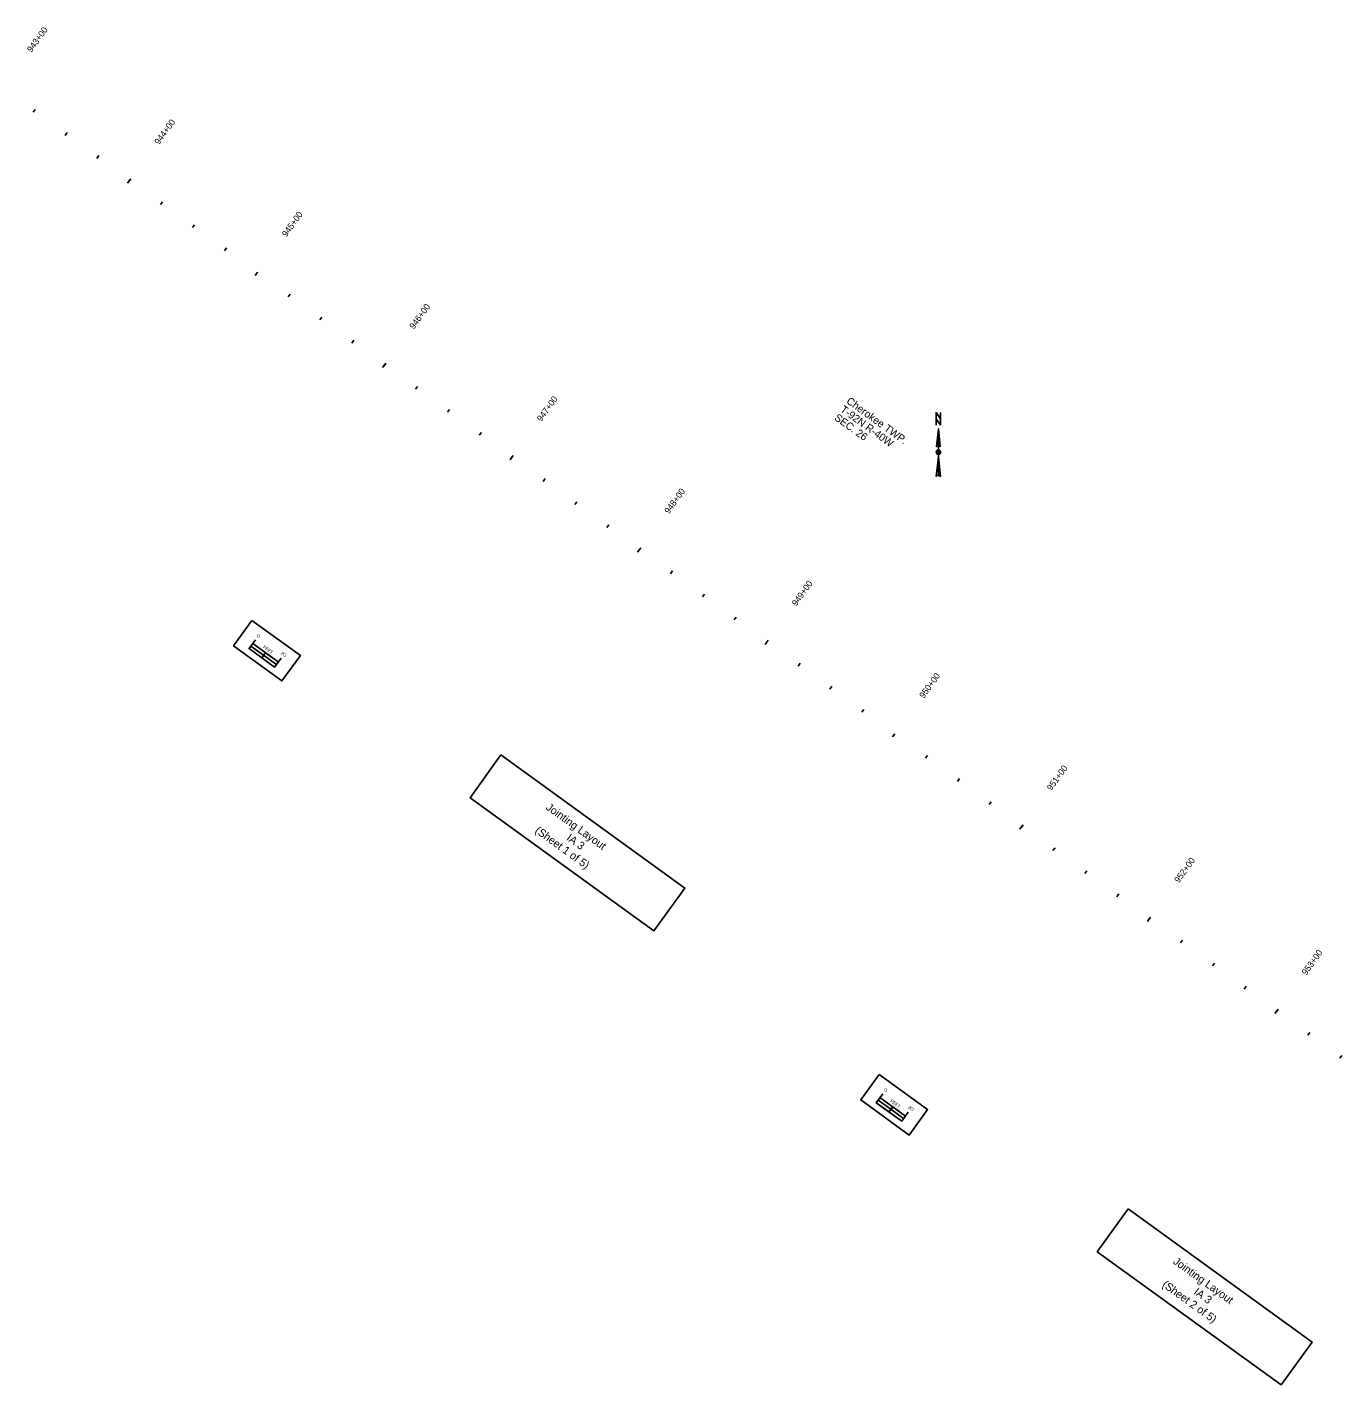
# Model space of a CAD drawing. Extents: x 14311466 to 14314811, y 8682098 to 8684603.
# Drawn here: x 14312293 to 14313129, y 8683212 to 8684075 of the extents above; entities that cross this region are included whole.
import ezdxf

# ---------------------------------------------------------------- set-up
doc = ezdxf.new("R2010")
doc.units = 0
for name, color, linetype in [('Draft_8', 7, 'Continuous'), ('Draft_9', 7, 'Continuous'), ('SheetText', 7, 'Continuous'), ('Text', 7, 'Continuous'), ('TextAlignmentLrg', 7, 'Continuous'), ('TextAlignmentSml', 7, 'Continuous')]:
    doc.layers.add(name, color=color, linetype=linetype)

msp = doc.modelspace()

# ---------------------------------------------------------------- linework, layer by layer
at = {"layer": 'Draft_8'}
for p, q in [((14312872.45, 8683819.95), (14312873.59, 8683808.54)), ((14312872.45, 8683819.95), (14312872.45, 8683790.28)), ((14312871.31, 8683808.54), (14312871.31, 8683808.54)), ((14312871.35, 8683808.64), (14312871.57, 8683808.88)), ((14312871.02, 8683789.71), (14312872.45, 8683802.26)), ((14312872.45, 8683803.69), (14312872.45, 8683803.69))]:
    msp.add_line(p, q, dxfattribs=at)
for points in [[(14312873.88, 8683822.23), (14312871.02, 8683826.22), (14312871.02, 8683830.21), (14312873.88, 8683826.22)], [(14312594.51, 8683612.67), (14312711.34, 8683528.07), (14312691.68, 8683500.91), (14312574.84, 8683585.5)]]:
    msp.add_lwpolyline(points, close=True, dxfattribs=at)
for points in [[(14312871.02, 8683822.23), (14312871.02, 8683830.21), (14312873.88, 8683826.22), (14312873.88, 8683830.21)], [(14312871.31, 8683808.54), (14312872.45, 8683819.95), (14312872.45, 8683809.11)], [(14312872.45, 8683803.69), (14312872.45, 8683805.11), (14312871.02, 8683805.11)], [(14312873.88, 8683805.11), (14312872.45, 8683805.11), (14312872.45, 8683806.54)], [(14312872.45, 8683790.28), (14312872.45, 8683802.26), (14312873.88, 8683789.71)]]:
    msp.add_lwpolyline(points, dxfattribs=at)
for centre, radius, start, end in [((14312872.45, 8683807.68), 1.43, 90.02039, 143.12574), ((14312872.45, 8683807.68), 1.43, 36.84806, 90.02184), ((14312872.45, 8683805.11), 1.43, 90, 180), ((14312872.45, 8683805.11), 1.43, 180, 270), ((14312872.45, 8683805.11), 1.43, 0, 90), ((14312872.45, 8683805.11), 1.43, 270, 360), ((14312872.45, 8683788.22), 2.07, 89.98939, 133.61895), ((14312872.45, 8683788.21), 2.07, 46.40206, 90.00064)]:
    msp.add_arc(centre, radius, start, end, dxfattribs=at)
at = {"layer": 'Draft_9'}
msp.add_lwpolyline([(14312993.02, 8683324.13), (14313109.85, 8683239.54), (14313090.19, 8683212.37), (14312973.35, 8683296.97)], close=True, dxfattribs=at)
at = {"layer": 'SheetText'}
for p, q in [((14312442.56, 8683674.36), (14312444.91, 8683677.6)), ((14312442.56, 8683674.36), (14312444.91, 8683677.6)), ((14312841.07, 8683385.83), (14312843.42, 8683389.07)), ((14312841.07, 8683385.83), (14312843.42, 8683389.07))]:
    msp.add_line(p, q, dxfattribs=at)
for points in [[(14312436.32, 8683698.14), (14312467.1, 8683675.86), (14312455.37, 8683659.66), (14312424.59, 8683681.94)], [(14312436.32, 8683698.14), (14312467.1, 8683675.86), (14312455.37, 8683659.66), (14312424.59, 8683681.94)], [(14312434.46, 8683680.23), (14312442.56, 8683674.36), (14312443.74, 8683676), (14312435.64, 8683681.86)], [(14312443.74, 8683676), (14312451.84, 8683670.13), (14312453.01, 8683671.74), (14312444.91, 8683677.6)], [(14312834.83, 8683409.61), (14312865.61, 8683387.32), (14312853.88, 8683371.12), (14312823.1, 8683393.41)], [(14312834.83, 8683409.61), (14312865.61, 8683387.32), (14312853.88, 8683371.12), (14312823.1, 8683393.41)], [(14312832.97, 8683391.69), (14312841.07, 8683385.83), (14312842.25, 8683387.46), (14312834.15, 8683393.32)], [(14312842.25, 8683387.46), (14312850.35, 8683381.59), (14312851.52, 8683383.2), (14312843.42, 8683389.07)]]:
    msp.add_lwpolyline(points, close=True, dxfattribs=at)
for points in [[(14312438.57, 8683685.9), (14312434.46, 8683680.23), (14312450.66, 8683668.5), (14312454.77, 8683674.17)], [(14312436.81, 8683683.47), (14312453.01, 8683671.74)], [(14312837.08, 8683397.36), (14312832.97, 8683391.69), (14312849.17, 8683379.96), (14312853.28, 8683385.63)], [(14312835.32, 8683394.93), (14312851.52, 8683383.2)]]:
    msp.add_lwpolyline(points, dxfattribs=at)
at = {"layer": 'TextAlignmentLrg'}
for p, q in [((14312358.02, 8683977.06), (14312359.3, 8683978.83)), ((14312439.73, 8683919.41), (14312438.3, 8683917.43)), ((14312520.01, 8683859.77), (14312521.29, 8683861.54)), ((14312601.01, 8683801.13), (14312602.29, 8683802.9)), ((14312682.01, 8683742.48), (14312683.29, 8683744.25)), ((14312763.01, 8683683.84), (14312764.29, 8683685.6)), ((14312844.72, 8683626.18), (14312843.29, 8683624.2)), ((14312925, 8683566.54), (14312926.28, 8683568.31)), ((14313006, 8683507.9), (14313007.28, 8683509.67)), ((14313087, 8683449.25), (14313088.28, 8683451.02))]:
    msp.add_line(p, q, dxfattribs=at)
at = {"layer": 'TextAlignmentSml'}
for p, q in [((14312297.27, 8684021.05), (14312298.55, 8684022.82)), ((14312317.52, 8684006.39), (14312318.8, 8684008.16)), ((14312337.77, 8683991.73), (14312339.05, 8683993.5)), ((14312358.74, 8683978.06), (14312357.3, 8683976.07)), ((14312378.27, 8683962.4), (14312379.55, 8683964.17)), ((14312398.52, 8683947.74), (14312399.8, 8683949.51)), ((14312418.77, 8683933.08), (14312420.05, 8683934.85)), ((14312439.73, 8683919.41), (14312438.3, 8683917.43)), ((14312459.27, 8683903.76), (14312460.55, 8683905.53)), ((14312479.52, 8683889.1), (14312480.8, 8683890.87)), ((14312499.76, 8683874.43), (14312501.05, 8683876.2)), ((14312520.73, 8683860.76), (14312519.3, 8683858.78)), ((14312540.26, 8683845.11), (14312541.54, 8683846.88)), ((14312560.51, 8683830.45), (14312561.79, 8683832.22)), ((14312580.76, 8683815.79), (14312582.04, 8683817.56)), ((14312601.73, 8683802.12), (14312600.29, 8683800.14)), ((14312621.26, 8683786.47), (14312622.54, 8683788.24)), ((14312641.51, 8683771.8), (14312642.79, 8683773.57)), ((14312661.76, 8683757.14), (14312663.04, 8683758.91)), ((14312682.73, 8683743.47), (14312681.29, 8683741.49)), ((14312702.26, 8683727.82), (14312703.54, 8683729.59)), ((14312722.51, 8683713.16), (14312723.79, 8683714.93)), ((14312742.76, 8683698.5), (14312744.04, 8683700.27)), ((14312763.73, 8683684.83), (14312762.29, 8683682.84)), ((14312783.26, 8683669.17), (14312784.54, 8683670.94)), ((14312803.51, 8683654.51), (14312804.79, 8683656.28)), ((14312823.76, 8683639.85), (14312825.04, 8683641.62)), ((14312844.72, 8683626.18), (14312843.29, 8683624.2)), ((14312864.26, 8683610.53), (14312865.54, 8683612.3)), ((14312884.51, 8683595.87), (14312885.79, 8683597.64)), ((14312904.75, 8683581.21), (14312906.04, 8683582.97)), ((14312925.72, 8683567.54), (14312924.29, 8683565.55)), ((14312945.25, 8683551.88), (14312946.53, 8683553.65)), ((14312965.5, 8683537.22), (14312966.78, 8683538.99)), ((14312985.75, 8683522.56), (14312987.03, 8683524.33)), ((14313006.72, 8683508.89), (14313005.28, 8683506.91)), ((14313026.25, 8683493.24), (14313027.53, 8683495.01)), ((14313046.5, 8683478.58), (14313047.78, 8683480.34)), ((14313066.75, 8683463.91), (14313068.03, 8683465.68)), ((14313087.72, 8683450.24), (14313086.28, 8683448.26)), ((14313107.25, 8683434.59), (14313108.53, 8683436.36)), ((14313127.5, 8683419.93), (14313128.78, 8683421.7))]:
    msp.add_line(p, q, dxfattribs=at)

# ---------------------------------------------------------------- texts
at = {"layer": 'Draft_8'}
for s, p in [('Jointing Layout', (14312622.62, 8683578.4)), ('(Sheet 1 of 5)', (14312615.67, 8683563.68)), ('IA 3', (14312635.76, 8683559.01))]:
    msp.add_text(s, height=5, rotation=324.09397, dxfattribs=at).set_placement(p)
at = {"layer": 'Draft_9'}
for s, p in [('Jointing Layout', (14313021.13, 8683289.86)), ('(Sheet 2 of 5)', (14313014.18, 8683275.14)), ('IA 3', (14313034.27, 8683270.47))]:
    msp.add_text(s, height=5, rotation=324.09397, dxfattribs=at).set_placement(p)
at = {"layer": 'SheetText'}
for s, p in [('O', (14312438.94, 8683688.1)), ('FEET', (14312443.1, 8683680.89)), ('2O', (14312454.42, 8683676.89)), ('O', (14312837.45, 8683399.56)), ('FEET', (14312841.61, 8683392.35)), ('2O', (14312852.93, 8683388.35))]:
    msp.add_text(s, height=2, rotation=324.09397, dxfattribs=at).set_placement(p)
at = {"layer": 'Text'}
for s, p in [('T-92N R-40W', (14312809.69, 8683831.27)), ('Cherokee TWP.', (14312813.54, 8683836.58)), ('SEC. 26', (14312805.89, 8683826.03))]:
    msp.add_text(s, height=4.8, rotation=324.0943, dxfattribs=at).set_placement(p)
at = {"layer": 'TextAlignmentLrg'}
for s, p in [('945+00', (14312458.23, 8683941.54)), ('950+00', (14312863.22, 8683648.31))]:
    msp.add_text(s, height=4.008, rotation=54.09397, dxfattribs=at).set_placement(p)
at = {"layer": 'TextAlignmentSml'}
for s, p in [('943+00', (14312296.24, 8684058.83)), ('944+00', (14312377.23, 8684000.19)), ('945+00', (14312458.23, 8683941.54)), ('946+00', (14312539.23, 8683882.9)), ('947+00', (14312620.23, 8683824.25)), ('948+00', (14312701.23, 8683765.61)), ('949+00', (14312782.22, 8683706.96)), ('950+00', (14312863.22, 8683648.31)), ('951+00', (14312944.22, 8683589.67)), ('952+00', (14313025.22, 8683531.02)), ('953+00', (14313106.22, 8683472.38))]:
    msp.add_text(s, height=4.008, rotation=54.09397, dxfattribs=at).set_placement(p)

doc.saveas('drawing.dxf')
